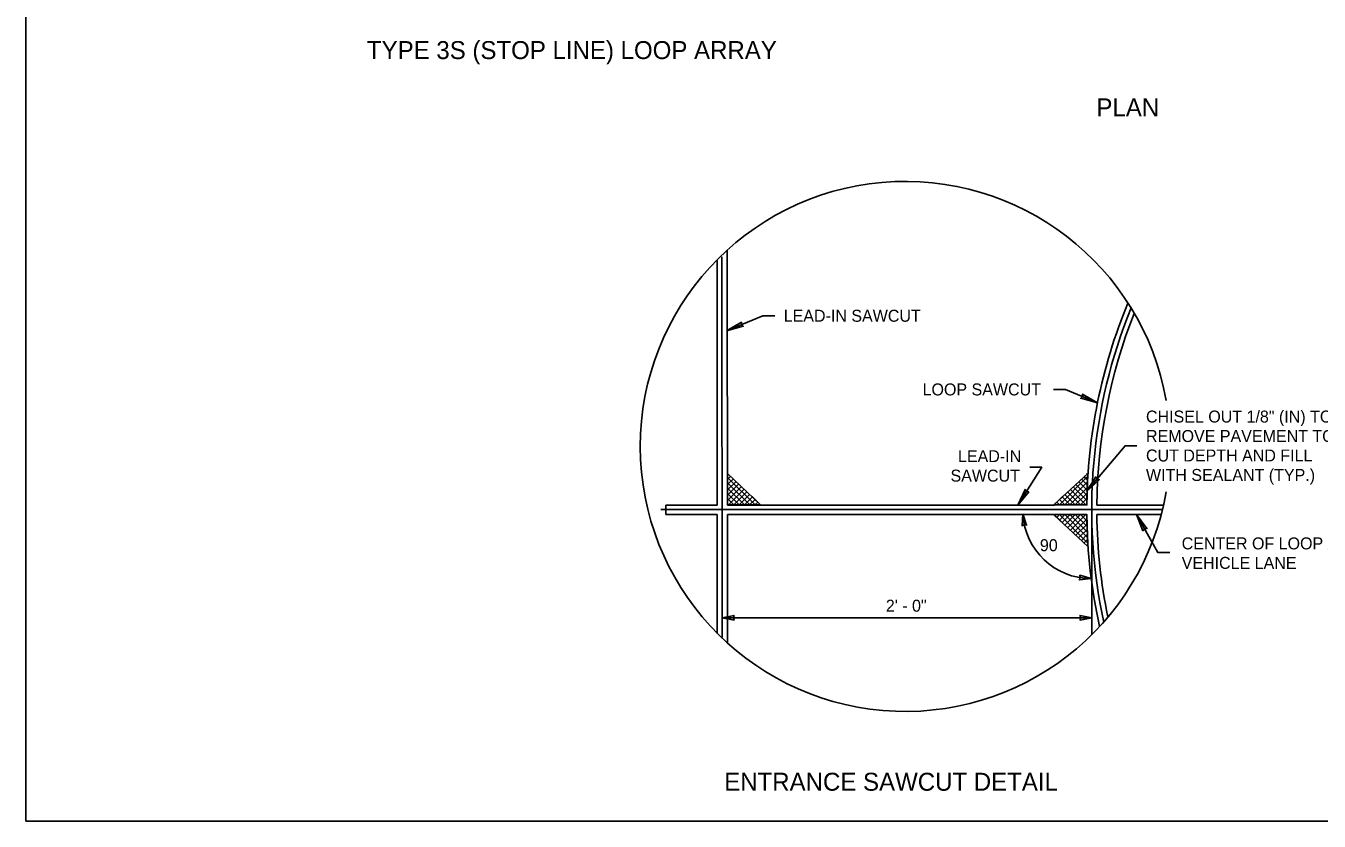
# Model space of a CAD drawing. Extents: x 99862 to 103680, y 99470 to 102076.
# Drawn here: x 99862 to 101589, y 100000 to 101062 of the extents above; entities that cross this region are included whole.
import ezdxf

# ---------------------------------------------------------------- set-up
doc = ezdxf.new("R2010")
doc.units = 0
for name, color, linetype in [('Level 1', 7, 'Continuous'), ('Level 15', 7, 'Continuous'), ('Level 18', 7, 'Continuous'), ('Level 20', 7, 'Continuous'), ('Level 27', 7, 'Continuous'), ('Level 60', 7, 'Continuous')]:
    doc.layers.add(name, color=color, linetype=linetype)

msp = doc.modelspace()

# ---------------------------------------------------------------- linework, layer by layer
at = {"layer": 'Level 1'}
msp.add_lwpolyline([(99862, 99999.5), (103151, 99999.5), (103151, 102075.5), (99862, 102075.5)], close=True, dxfattribs=at)
at = {"layer": 'Level 15'}
for p, q in [((100792.3, 100244.6), (100791.8, 100753.2)), ((100710.1, 100415.5), (101379.4, 100415.5)), ((101285.7, 100415.6), (101285.7, 100249.2))]:
    msp.add_line(p, q, dxfattribs=at)
for points in [[(100798, 100654.2), (100846.3, 100674.3), (100862.3, 100674.4)], [(101293.3, 100558.1), (101250.6, 100575.9), (101234.6, 100576)], [(101346.2, 100500.8), (101330.2, 100500.8), (101278.8, 100439.8)], [(101203, 100472.2), (101219, 100472.2), (101187, 100421.5)], [(101389.9, 100358.4), (101373.9, 100358.4), (101345.6, 100408.8)], [(100792.2, 100271.2), (101285.8, 100271.2)]]:
    msp.add_lwpolyline(points, dxfattribs=at)
for points in [[(100798, 100654.2), (100820.2, 100660.3), (100818, 100662.6), (100817.9, 100665.8)], [(101293.3, 100558.1), (101271.1, 100564.2), (101273.2, 100566.5), (101273.4, 100569.7)], [(101278.8, 100439.8), (101291.2, 100459.2), (101292.8, 100456.4), (101295.8, 100455.3)], [(101187, 100421.5), (101196.7, 100442.4), (101198.6, 100439.9), (101201.7, 100439.2)], [(101193.6, 100409.9), (101192.7, 100393.9), (101195.7, 100395), (101198.8, 100394.7)], [(101345.6, 100408.8), (101354.2, 100387.4), (101356.3, 100389.8), (101359.4, 100390.3)], [(101285.2, 100323.4), (101269.3, 100321.7), (101270.3, 100324.7), (101269.8, 100327.9)], [(100792.2, 100271.2), (100808, 100268.1), (100807.2, 100271.2), (100808, 100274.3)], [(101285.8, 100271.2), (101270.1, 100268.1), (101270.8, 100271.2), (101270.1, 100274.3)]]:
    msp.add_lwpolyline(points, close=True, dxfattribs=at)
for centre, radius, start, end in [((101036.6, 100499.9), 353.9, 9.9887, 350.1679), ((101999.2, 100415.7), 713.5, 157.8326, 192.1929), ((101285.2, 100415.2), 91.8, 183.3178, 270)]:
    msp.add_arc(centre, radius, start, end, dxfattribs=at)
at = {"layer": 'Level 18'}
for p, q in [((100785.2, 100726.3), (100785.2, 100748.3)), ((100798.8, 100761.5), (100798.9, 100712.1)), ((100785.4, 100421.5), (100785.2, 100726.3)), ((100798.9, 100712.1), (100799.1, 100421.5)), ((100716.7, 100408.8), (100716.7, 100421.5)), ((100716.7, 100421.5), (100785.4, 100421.5)), ((100799.1, 100421.5), (101022.4, 100421.5)), ((101022.4, 100421.5), (101236, 100421.5)), ((101292.6, 100421.5), (101382.1, 100421.5)), ((100785.4, 100408.8), (100716.7, 100408.8)), ((100785.5, 100250), (100785.4, 100408.8)), ((100799.1, 100408.8), (100799.2, 100237.8)), ((101009.7, 100408.8), (100799.1, 100408.8)), ((101235.6, 100408.8), (101009.7, 100408.8)), ((101378.4, 100408.8), (101292.6, 100408.8))]:
    msp.add_line(p, q, dxfattribs=at)
for points in [[(100842.5, 100421.8), (100799.3, 100421.8), (100799.3, 100463.8), (100842.8, 100422.5)], [(101236, 100421.8), (101279.2, 100421.8), (101280.5, 100463.8), (101235.6, 100422.5)], [(101236, 100408.8), (101279.2, 100408.8), (101280.5, 100366.3), (101235.6, 100408.1)]]:
    msp.add_lwpolyline(points, close=True, dxfattribs=at)
for centre, radius, start, end in [((101999.1, 100415.3), 720, 157.4676, 179.4858), ((102005.6, 100415.7), 713, 158.456, 179.5348), ((101999.1, 100415.4), 720, 180.5239, 192.5127), ((102005.6, 100415.7), 713, 180.5556, 191.5985)]:
    msp.add_arc(centre, radius, start, end, dxfattribs=at)
at = {"layer": 'Level 27'}
for p, q in [((100799.3, 100463.1), (100799.8, 100463.6)), ((100799.3, 100456), (100803.5, 100460.1)), ((100799.3, 100458.4), (100836, 100421.8)), ((100799.3, 100448.9), (100807.1, 100456.7)), ((101280.3, 100459.6), (101242.5, 100421.8)), ((101279.6, 100448.4), (101272.1, 100456)), ((101279.2, 100456), (101275.8, 100459.4)), ((101279.2, 100463.1), (101278.6, 100463.6)), ((100799.3, 100441.8), (100810.7, 100453.2)), ((100799.3, 100451.4), (100828.9, 100421.8)), ((100799.3, 100434.8), (100814.3, 100449.8)), ((100799.3, 100427.7), (100817.9, 100446.3)), ((100799.3, 100444.3), (100821.8, 100421.8)), ((100799.3, 100437.2), (100814.7, 100421.8)), ((100800.5, 100421.8), (100821.5, 100442.8)), ((100807.6, 100421.8), (100825.2, 100439.4)), ((101279.8, 100452.1), (101249.6, 100421.8)), ((101270.9, 100421.8), (101253.7, 100439)), ((101279.5, 100444.7), (101256.7, 100421.8)), ((101278, 100421.8), (101257.3, 100442.4)), ((101279.2, 100427.7), (101261, 100445.8)), ((101279.2, 100437.2), (101263.7, 100421.8)), ((101279.2, 100434.8), (101264.7, 100449.2)), ((101279.2, 100441.8), (101268.4, 100452.6)), ((100799.3, 100430.2), (100807.7, 100421.8)), ((100799.3, 100423.1), (100800.6, 100421.8)), ((100814.6, 100421.8), (100828.8, 100435.9)), ((100821.7, 100421.8), (100832.4, 100432.5)), ((100828.8, 100421.8), (100836, 100429)), ((100832, 100432.9), (100842.7, 100422.2)), ((100835.9, 100421.8), (100839.6, 100425.6)), ((101246.5, 100432.9), (101235.8, 100422.2)), ((101242.6, 100421.8), (101238.9, 100425.6)), ((101249.7, 100421.8), (101242.5, 100429)), ((101256.8, 100421.8), (101246.1, 100432.5)), ((101263.8, 100421.8), (101249.7, 100435.9)), ((101279.2, 100430.2), (101270.8, 100421.8)), ((101279.2, 100423.1), (101277.9, 100421.8)), ((101246.5, 100397.7), (101235.8, 100408.4)), ((101242.6, 100408.8), (101238.9, 100405)), ((101249.7, 100408.8), (101242.5, 100401.6)), ((101280.1, 100371.2), (101242.5, 100408.8)), ((101256.8, 100408.8), (101246.1, 100398.1)), ((101279.6, 100378.7), (101249.6, 100408.8)), ((101263.8, 100408.8), (101249.7, 100394.6)), ((101270.9, 100408.8), (101253.3, 100391.2)), ((101279.2, 100386.3), (101256.7, 100408.8)), ((101278, 100408.8), (101257.2, 100388)), ((101279.2, 100402.9), (101260.9, 100384.6)), ((101279.2, 100393.3), (101263.7, 100408.8)), ((101279.2, 100400.4), (101270.8, 100408.8)), ((101279.2, 100407.5), (101277.9, 100408.8)), ((101279.2, 100395.8), (101264.5, 100381.2)), ((101279.2, 100388.7), (101268.2, 100377.8)), ((101279.2, 100381.7), (101271.9, 100374.4)), ((101280, 100375.4), (101275.5, 100371)), ((101279.2, 100367.5), (101278.6, 100367))]:
    msp.add_line(p, q, dxfattribs=at)
at = {"layer": 'Level 60'}
msp.add_line((99862, 99999.5), (99862, 99999.5), dxfattribs=at)

# ---------------------------------------------------------------- texts
at = {"layer": 'Level 20'}
for s, height, p in [('TYPE 3S (STOP LINE) LOOP ARRAY', 24, (100317.6, 101017.2)), ('PLAN', 24, (101292, 100940.7)), ('LEAD-IN SAWCUT', 16, (100874.3, 100666.4)), ('CHISEL OUT 1/8" (IN) TO 1/2" (IN) CORNER', 16, (101358.2, 100531.8)), ('REMOVE PAVEMENT TO SAW-', 16, (101358.2, 100505.8)), ('LEAD-IN', 16, (101107.1, 100478.9)), ('CUT DEPTH AND FILL ', 16, (101358.2, 100479.8)), ('SAWCUT', 16, (101097.1, 100452.9)), ('WITH SEALANT (TYP.)', 16, (101358.2, 100453.8)), ('90', 16, (101216.5, 100360)), ('CENTER OF LOOP AND', 16, (101405.9, 100362.4)), ('VEHICLE LANE', 16, (101405.9, 100336.4)), ('2\' - 0"', 16, (101010.7, 100279.2)), ('ENTRANCE SAWCUT DETAIL', 24, (100794.8, 100040.1))]:
    msp.add_text(s, height=height, dxfattribs=at).set_placement(p)
msp.add_text('LOOP SAWCUT', height=16, rotation=360, dxfattribs=at).set_placement((101059.8, 100568))

doc.saveas('drawing.dxf')
